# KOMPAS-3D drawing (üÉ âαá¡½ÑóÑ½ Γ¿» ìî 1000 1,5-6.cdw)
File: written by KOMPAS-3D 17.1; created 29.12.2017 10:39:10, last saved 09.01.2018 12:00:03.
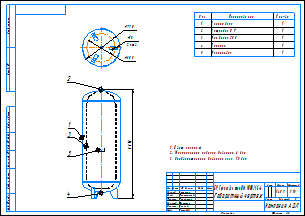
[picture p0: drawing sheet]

Sheet 1: A3, landscape, title-block layout from C:\Лощинин\GRAPHIC.LYT style 1

Title block, sheet 1: name: БР Гранлевел тип НМ 1000/1,5-6 / Габаритный чертеж; mass: 145,9; sheets: 1; sheet format: A3; stored path: \\Fsk1\files\АП\20_PKO\02_Насосное направление\Разработка\04_Проекты разные\Баки\КД действующая\Баки Flexcon R\Компас\Чертежи\БР Гранлевел тип НМ 1000 1,5-6.cdw; drawn by: Лощинин; checked by: Хантимеров

Views: Проекционный вид 3
Referenced files in \\Fsk1\files\АП\20_PKO\02_Насосное направление\Разработка\04_Проекты разные\Баки\КД действующая\Баки Flexcon R\Компас\: 1000 литров.a3d, 16902_Flexcon_1000_1-6.m3d
Referenced files in C:\Лощинин\: GRAPHIC.LYT
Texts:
  IvAn
  ADL
  Поз.
  Кол-во
  Корпус бака
  Мембрана SBR
  Патрубок G 1"
  Ниппель
  Маркировка
  АДЛ
  Цвет: красный
  Максимальное рабочее давление: 6 бар
  Предварительное давление газа: 1,5 бар
  ACAD_ISO03W100_RGB_223_127_255_SC_0.063_THICK_0.05
  ACAD_ISO03W100_RGB_223_127_255_SC_1_THICK_0.05
  Лит-Масса-Масштаб
  Материал-Предприятие
  Масштаб
  Изм.
  Лист
  № докум.
  Подп.
  Дата
  Лит.
  Разраб.
  Пров.
  Т.контр.
  Курлыкина
  Листов
  Нач.отд.
  Щетинин
  Н.контр.
  Долгов
  Утв.
  Рашидов
  Компания АДЛ
  Изменение
  Номер документа
  Подпись
  Обозначение документа
  Наименование изделия
  Масса изделия по ГОСТ 2.109-73
  Порядковый номер листа
  Общее количество листов в документе
  Характер работы, выполненной лицом, подписавшим документ
  Наименование или индекс предприятия, выпускающего документ
  Инв. № подл.
  Подп. и дата
  Взам. инв. №
  Инв. № дубл.
  Инвентарный номер подлинника по ГОСТ 2.501-68
  Подпись принявшего подлинник в отдел технической документации
  Инвентарный номер подлинника, взамен которого выпущен данный подлинник
  Инвентарный номер дубликата по ГОСТ 2.502-68
  Подпись принявшего дубликат в отдел технической документации
  Справ. №
  Перв. примен.
  Обозначение документа, взамен или на основании которого выпущен данный документ
  Обозначение документа, в котором впервые записан данный документ
  Подпись лица, копировавшего чертеж
  Обозначение формата листа
Dimensions and other numbers on the sheet: 1; 3; 2; 4; 5; 2270; 1:15; 145,9; 16902_Flexcon_1000_1-6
